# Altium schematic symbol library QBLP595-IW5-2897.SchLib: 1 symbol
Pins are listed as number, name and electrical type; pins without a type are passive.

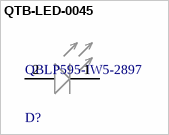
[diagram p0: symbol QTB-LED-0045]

## QTB-LED-0045
designator D?, comment QBLP595-IW5-2897
LED WHITE DIFFUSED 0402 SMD; Manufacturer: QT Brightek (QTB); Luminous Intensity: 115mcd; Viewing Angle: 150°; Forward Voltage: 2.9V; Test Current: 20mA; Lens Style: Flat; Lens Color: Yellow; Lens Size: 0.5mm
footprint FP-QBLP595-IW5-2897-MFG
pins: 1 CATHODE (-), 2 ANODE (+)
